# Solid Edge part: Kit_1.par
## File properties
Sűrűség: 0,000 kg/m^3
Pontosság: 0,990
Author: ahadarics
Last saved by: ahadarics
Revision: 77
Username: ahadarics
Dokumentum tartalom típus: 0
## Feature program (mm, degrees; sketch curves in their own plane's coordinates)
base feature "unnamed BaseFeature 1"
sketch for "Furat_1" plane through (0, -49.25, 13.5) normal (0, 0, 1) x-axis (0, 1, 0)
  hole centre (0.25, 0) bore radius 4.283
hole "Furat_1" nominal diameter 9.728 finite  ThreadDepth = 7.5 mm
thread "unnamed Thread 1"
chamfer "Letörés_1" setback 1.5
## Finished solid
Body 1: solid body, 83 faces, 112 edges, 38 vertices, 1 internal void.
  Faces by surface: cylinder 27, plane 27, cone 19, torus 9, spun 1
  Edges by curve: circle 73, line 23, intersection 12, spline 4
Bounding box of the edges (mm; curved faces can reach further): 30.000 x 39.500 x 28.500, from (-15, -79, -15) to (15, -39.5, 13.5).
Cylindrical faces by radius (mm): R0.875 x1, R0.9 x1, R1.7 x1, R1.75 x1, R3 x1, R4.25 x1, R4.275 x3, R4.283 x2, R5.25 x2, R5.55 x1, R6 x1, R6.5 x3, R7 x1, R7.05 x1, R8.05 x1, R8.1 x1, R9.85 x1, R11 x2, R13.5 x1, R15 x1
Conical faces (half-angle, radius in mm at the cone's reference point): 0.1788 deg R6.7706 x1, 15 deg R8.05 x1, 17.2279 deg R5.55 x1, 19.7315 deg R5.0176 x1, 21.0856 deg R5.55 x1, 21.5244 deg R6.2703 x1, 30 deg R1.8366 x1, 30 deg R5.375 x1, 45 deg R1.55 x2, 45 deg R4.275 x1, 45 deg R4.35 x1, 45 deg R7.15 x1, 45 deg R7.2 x1, 45 deg R11 x1, 59 deg R1 x2, 59 deg R2.1415 x1, 60 deg R10.425 x1
Toroidal faces (ring radius, tube radius in mm): R3 r3 x1, R4.6345 r0.2 x1, R5.2 r0.2 x1, R5.3 r0.3 x1, R6.6424 r0.4 x1, R6.85 r0.2 x1, R7.85 r0.2 x1, R7.9 r0.2 x2
Planar faces by outward normal: +x 1, +y 7, +z 6, -x 1, -y 11, -z 1
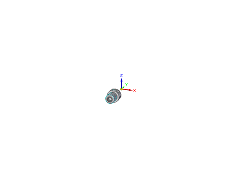
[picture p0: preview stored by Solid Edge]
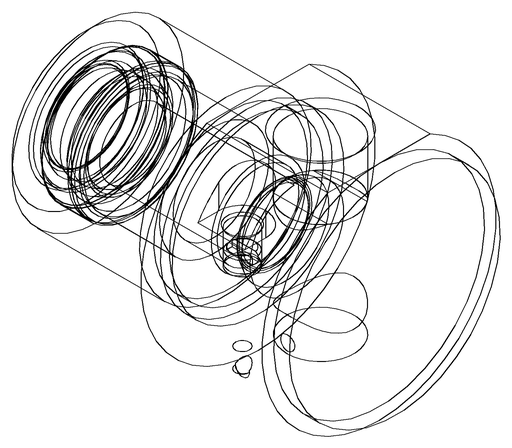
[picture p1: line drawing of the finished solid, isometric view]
